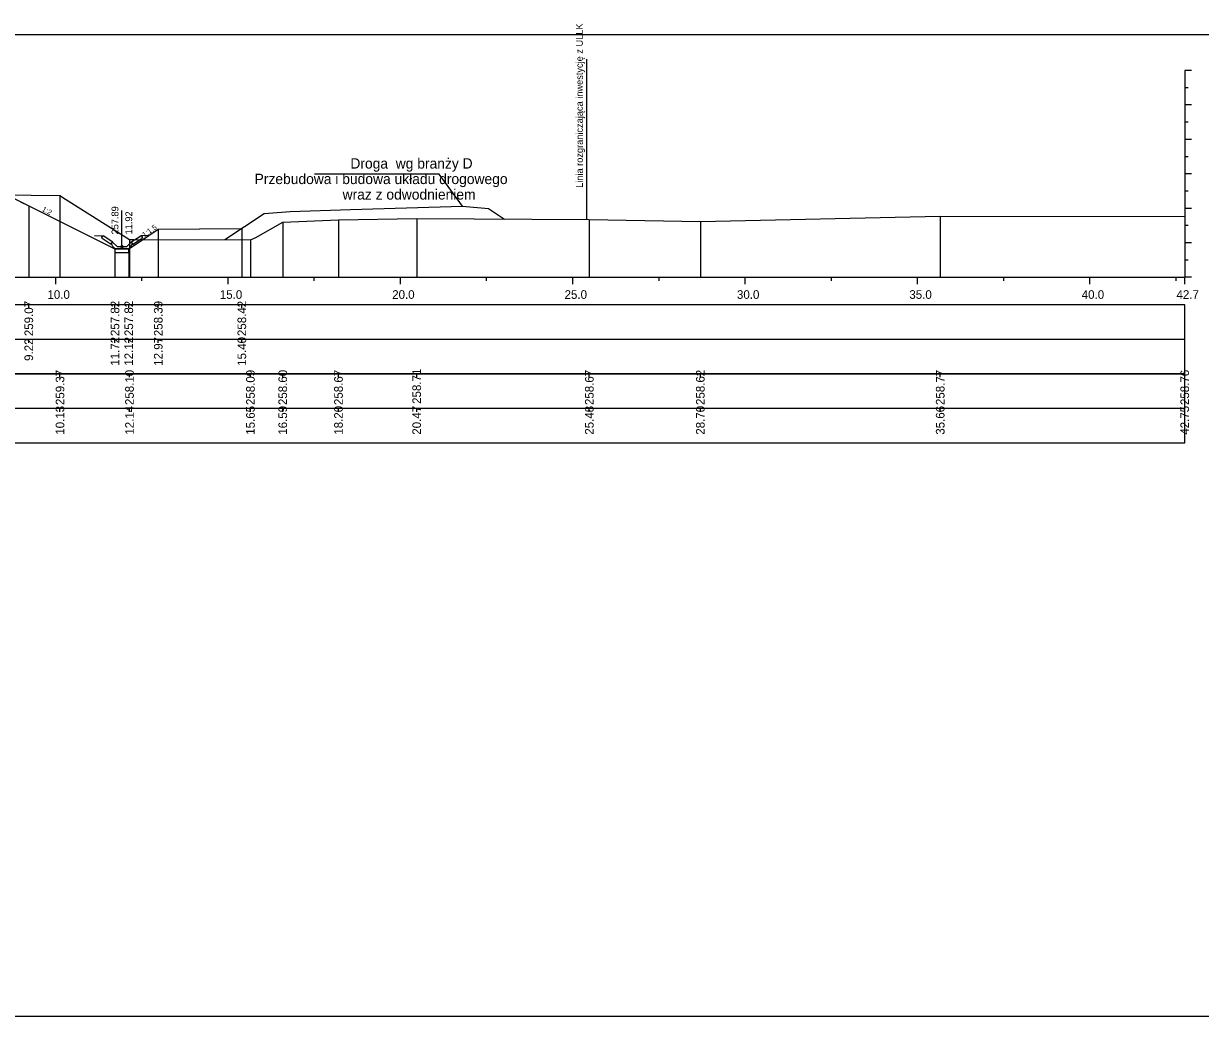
# Model space of a CAD drawing. Extents: x 6516023 to 6560129, y 5513077 to 5529206.
# Drawn here: x 6517046.78 to 6517080.92, y 5514518.16 to 5514546.97 of the extents above; entities that cross this region are included whole.
import ezdxf

# ---------------------------------------------------------------- set-up
doc = ezdxf.new("R2010")
doc.units = 0
for name, color, linetype in [('IR_default', 7, 'Continuous'), ('TOR_PRZEK_P-inne branze', 7, 'Continuous'), ('TOR_PRZEK_P-odwodnienie', 7, 'Continuous'), ('TOR_PRZEK_P-opisy', 7, 'Continuous'), ('TOR_PRZEK_P-tabelka istniejace', 7, 'Continuous'), ('TOR_PRZEK_P-tabelka projektowane', 7, 'Continuous'), ('TOR_PRZEK_P-teren istniejacy', 7, 'Continuous'), ('TOR_PRZEK_P-uklad odniesienia', 7, 'Continuous'), ('TOR_PRZEK_P-warstwa ochronna II', 7, 'Continuous'), ('TOR_PS_T-granica PKP-projektowana', 7, 'Continuous'), ('TOR_RAMKI-ramka+tabelka 1', 7, 'Continuous')]:
    doc.layers.add(name, color=color, linetype=linetype)

msp = doc.modelspace()

# ---------------------------------------------------------------- linework, layer by layer
at = {"layer": 'IR_default'}
msp.add_lwpolyline([(6517046.697, 5514541.797), (6517046.933, 5514541.679), (6517048.755, 5514540.768), (6517049.432, 5514540.429), (6517049.724, 5514540.429), (6517049.832, 5514540.429), (6517050.259, 5514540.713), (6517050.417, 5514540.819), (6517050.614, 5514540.95), (6517050.687, 5514540.999), (6517053.08, 5514541.023), (6517053.112, 5514541.023)], dxfattribs=at)
at = {"layer": 'TOR_PRZEK_P-inne branze'}
for p, q in [((6517058.841, 5514542.601), (6517055.217, 5514542.601)), ((6517059.517, 5514541.666), (6517058.841, 5514542.601))]:
    msp.add_line(p, q, dxfattribs=at)
msp.add_lwpolyline([(6517052.624, 5514540.698), (6517053.763, 5514541.457), (6517054.514, 5514541.517), (6517056.265, 5514541.569), (6517059.517, 5514541.666), (6517060.267, 5514541.606), (6517060.731, 5514541.297)], dxfattribs=at)
at = {"layer": 'TOR_PRZEK_P-odwodnienie'}
for p, q in [((6517049.633, 5514540.499), (6517049.633, 5514541.543)), ((6517049.368, 5514540.625), (6517049.088, 5514540.812)), ((6517049.897, 5514540.625), (6517050.178, 5514540.812)), ((6517049.324, 5514540.558), (6517049.063, 5514540.732)), ((6517049.335, 5514540.575), (6517049.324, 5514540.558)), ((6517049.325, 5514540.594), (6517049.373, 5514540.618)), ((6517049.368, 5514540.625), (6517049.36, 5514540.612)), ((6517049.493, 5514540.499), (6517049.373, 5514540.618)), ((6517049.443, 5514540.429), (6517049.823, 5514540.429)), ((6517049.493, 5514540.499), (6517049.773, 5514540.499)), ((6517049.773, 5514540.499), (6517049.893, 5514540.618)), ((6517049.893, 5514540.618), (6517049.94, 5514540.594)), ((6517049.897, 5514540.625), (6517049.906, 5514540.612)), ((6517049.931, 5514540.575), (6517049.942, 5514540.558)), ((6517049.942, 5514540.558), (6517050.203, 5514540.732))]:
    msp.add_line(p, q, dxfattribs=at)
for points in [[(6517048.841, 5514540.823), (6517049.088, 5514540.812)], [(6517049.038, 5514540.785), (6517049.088, 5514540.812)], [(6517049.038, 5514540.785), (6517049.063, 5514540.732)], [(6517050.424, 5514540.823), (6517050.178, 5514540.812)], [(6517050.228, 5514540.785), (6517050.178, 5514540.812)], [(6517050.228, 5514540.785), (6517050.203, 5514540.732)], [(6517049.36, 5514540.612), (6517049.325, 5514540.594)], [(6517049.373, 5514540.499), (6517049.325, 5514540.594)], [(6517049.325, 5514540.594), (6517049.335, 5514540.575)], [(6517049.443, 5514540.429), (6517049.373, 5514540.499)], [(6517049.432, 5514540.429), (6517049.432, 5514540.429), (6517049.432, 5514540.429), (6517049.432, 5514540.428), (6517049.432, 5514540.429), (6517049.433, 5514540.428), (6517049.432, 5514540.429), (6517049.433, 5514540.429)], [(6517049.433, 5514540.428), (6517049.432, 5514540.429), (6517049.433, 5514540.428), (6517049.432, 5514540.428), (6517049.433, 5514540.428), (6517049.433, 5514540.428), (6517049.433, 5514540.428), (6517049.433, 5514540.429)], [(6517049.833, 5514540.429), (6517049.433, 5514540.429), (6517049.433, 5514540.329), (6517049.833, 5514540.329), (6517049.833, 5514540.429)], [(6517049.823, 5514540.429), (6517049.893, 5514540.499)], [(6517049.832, 5514540.429), (6517049.832, 5514540.429), (6517049.832, 5514540.429), (6517049.832, 5514540.428), (6517049.832, 5514540.429), (6517049.833, 5514540.428), (6517049.832, 5514540.429), (6517049.833, 5514540.429)], [(6517049.833, 5514540.428), (6517049.832, 5514540.429), (6517049.833, 5514540.428), (6517049.832, 5514540.428), (6517049.833, 5514540.428), (6517049.833, 5514540.428), (6517049.833, 5514540.428), (6517049.833, 5514540.429)], [(6517049.893, 5514540.499), (6517049.94, 5514540.594)], [(6517049.906, 5514540.612), (6517049.941, 5514540.594)], [(6517049.941, 5514540.594), (6517049.931, 5514540.575)]]:
    msp.add_lwpolyline(points, dxfattribs=at)
msp.add_circle((6517049.633, 5514540.499), 0.035, dxfattribs=at)
at = {"layer": 'TOR_PRZEK_P-tabelka istniejace'}
for p, q in [((6517047.838, 5514536.706), (6517047.838, 5514536.806)), ((6517049.854, 5514536.706), (6517049.854, 5514536.806)), ((6517053.362, 5514536.706), (6517053.362, 5514536.806)), ((6517054.299, 5514536.706), (6517054.299, 5514536.806)), ((6517055.916, 5514536.706), (6517055.916, 5514536.806)), ((6517058.184, 5514536.706), (6517058.184, 5514536.806)), ((6517063.192, 5514536.706), (6517063.192, 5514536.806)), ((6517066.412, 5514536.706), (6517066.412, 5514536.806)), ((6517073.37, 5514536.706), (6517073.37, 5514536.806)), ((6517080.463, 5514536.706), (6517080.463, 5514536.806)), ((6516996.663, 5514535.806), (6517080.463, 5514535.806)), ((6517047.838, 5514535.706), (6517047.838, 5514535.806)), ((6517049.854, 5514535.706), (6517049.854, 5514535.806)), ((6517053.362, 5514535.706), (6517053.362, 5514535.806)), ((6517054.299, 5514535.706), (6517054.299, 5514535.806)), ((6517055.916, 5514535.706), (6517055.916, 5514535.806)), ((6517058.184, 5514535.706), (6517058.184, 5514535.806)), ((6517063.192, 5514535.706), (6517063.192, 5514535.806)), ((6517066.412, 5514535.706), (6517066.412, 5514535.806)), ((6517073.37, 5514535.706), (6517073.37, 5514535.806)), ((6517080.463, 5514535.706), (6517080.463, 5514535.806))]:
    msp.add_line(p, q, dxfattribs=at)
for points in [[(6517047.838, 5514541.978), (6517047.838, 5514539.806), (6517047.838, 5514539.676), (6517047.838, 5514539.606)], [(6517054.299, 5514541.206), (6517054.299, 5514539.806), (6517054.299, 5514539.676), (6517054.299, 5514539.606)], [(6517055.916, 5514541.277), (6517055.916, 5514539.806), (6517055.916, 5514539.676), (6517055.916, 5514539.606)], [(6517058.184, 5514541.316), (6517058.184, 5514539.806), (6517058.184, 5514539.676), (6517058.184, 5514539.606)], [(6517063.192, 5514541.279), (6517063.192, 5514539.806), (6517063.192, 5514539.676), (6517063.192, 5514539.606)], [(6517066.412, 5514541.228), (6517066.412, 5514539.806), (6517066.412, 5514539.676), (6517066.412, 5514539.606)], [(6517073.37, 5514541.378), (6517073.37, 5514539.806), (6517073.37, 5514539.676), (6517073.37, 5514539.606)], [(6517080.463, 5514541.37), (6517080.463, 5514539.806), (6517080.463, 5514539.676), (6517080.463, 5514539.606)], [(6517049.854, 5514540.706), (6517049.854, 5514539.806), (6517049.854, 5514539.676), (6517049.854, 5514539.606)], [(6517053.362, 5514540.696), (6517053.362, 5514539.806), (6517053.362, 5514539.676), (6517053.362, 5514539.606)]]:
    msp.add_lwpolyline(points, dxfattribs=at)
msp.add_lwpolyline([(6516996.663, 5514536.806), (6516996.663, 5514534.806), (6517080.463, 5514534.806), (6517080.463, 5514536.806)], close=True, dxfattribs=at)
at = {"layer": 'TOR_PRZEK_P-tabelka projektowane'}
for p, q in [((6517046.933, 5514538.706), (6517046.933, 5514538.806)), ((6517049.433, 5514538.706), (6517049.433, 5514538.806)), ((6517049.833, 5514538.706), (6517049.833, 5514538.806)), ((6517050.688, 5514538.706), (6517050.688, 5514538.806)), ((6517053.112, 5514538.706), (6517053.112, 5514538.806)), ((6516996.663, 5514537.806), (6517080.463, 5514537.806)), ((6517046.933, 5514537.706), (6517046.933, 5514537.806)), ((6517049.433, 5514537.706), (6517049.433, 5514537.806)), ((6517049.833, 5514537.706), (6517049.833, 5514537.806)), ((6517050.688, 5514537.706), (6517050.688, 5514537.806)), ((6517053.112, 5514537.706), (6517053.112, 5514537.806))]:
    msp.add_line(p, q, dxfattribs=at)
for points in [[(6517046.933, 5514541.679), (6517046.933, 5514539.806), (6517046.933, 5514539.676), (6517046.933, 5514539.606)], [(6517050.688, 5514540.998), (6517050.688, 5514539.806), (6517050.688, 5514539.676), (6517050.688, 5514539.606)], [(6517053.112, 5514541.023), (6517053.112, 5514539.806), (6517053.112, 5514539.676), (6517053.112, 5514539.606)], [(6517049.433, 5514540.428), (6517049.433, 5514539.806), (6517049.433, 5514539.676), (6517049.433, 5514539.606)], [(6517049.833, 5514540.428), (6517049.833, 5514539.806), (6517049.833, 5514539.676), (6517049.833, 5514539.606)]]:
    msp.add_lwpolyline(points, dxfattribs=at)
msp.add_lwpolyline([(6516996.663, 5514538.806), (6516996.663, 5514536.806), (6517080.463, 5514536.806), (6517080.463, 5514538.806)], close=True, dxfattribs=at)
at = {"layer": 'TOR_PRZEK_P-teren istniejacy'}
msp.add_lwpolyline([(6517045.321, 5514542.013), (6517047.838, 5514541.978), (6517047.998, 5514541.878), (6517049.854, 5514540.706), (6517049.984, 5514540.706), (6517053.362, 5514540.696), (6517053.523, 5514540.761), (6517054.299, 5514541.206), (6517055.916, 5514541.277), (6517058.184, 5514541.316), (6517063.192, 5514541.279), (6517066.412, 5514541.228), (6517073.37, 5514541.378), (6517080.463, 5514541.37)], dxfattribs=at)
at = {"layer": 'TOR_PRZEK_P-uklad odniesienia'}
for p, q in [((6517080.463, 5514545.606), (6517080.463, 5514539.606)), ((6517080.663, 5514545.606), (6517080.463, 5514545.606)), ((6517080.563, 5514545.106), (6517080.463, 5514545.106)), ((6517080.663, 5514544.606), (6517080.463, 5514544.606)), ((6517080.563, 5514544.106), (6517080.463, 5514544.106)), ((6517080.663, 5514543.606), (6517080.463, 5514543.606)), ((6517080.563, 5514543.106), (6517080.463, 5514543.106)), ((6517080.663, 5514542.606), (6517080.463, 5514542.606)), ((6517080.563, 5514542.106), (6517080.463, 5514542.106)), ((6517080.663, 5514541.606), (6517080.463, 5514541.606)), ((6517080.563, 5514541.106), (6517080.463, 5514541.106)), ((6517080.663, 5514540.606), (6517080.463, 5514540.606)), ((6517080.563, 5514540.106), (6517080.463, 5514540.106)), ((6517000.463, 5514539.606), (6517080.463, 5514539.606)), ((6517047.713, 5514539.406), (6517047.713, 5514539.606)), ((6517050.213, 5514539.506), (6517050.213, 5514539.606)), ((6517052.713, 5514539.406), (6517052.713, 5514539.606)), ((6517055.213, 5514539.506), (6517055.213, 5514539.606)), ((6517057.713, 5514539.406), (6517057.713, 5514539.606)), ((6517060.213, 5514539.506), (6517060.213, 5514539.606)), ((6517062.713, 5514539.406), (6517062.713, 5514539.606)), ((6517065.213, 5514539.506), (6517065.213, 5514539.606)), ((6517067.713, 5514539.406), (6517067.713, 5514539.606)), ((6517070.213, 5514539.506), (6517070.213, 5514539.606)), ((6517072.713, 5514539.406), (6517072.713, 5514539.606)), ((6517075.213, 5514539.506), (6517075.213, 5514539.606)), ((6517077.713, 5514539.406), (6517077.713, 5514539.606)), ((6517080.213, 5514539.506), (6517080.213, 5514539.606)), ((6517080.463, 5514539.406), (6517080.463, 5514539.606)), ((6517080.663, 5514539.606), (6517080.463, 5514539.606))]:
    msp.add_line(p, q, dxfattribs=at)
at = {"layer": 'TOR_PRZEK_P-warstwa ochronna II'}
msp.add_lwpolyline([(6517021.393, 5514541.001), (6517021.652, 5514540.998), (6517022.237, 5514540.608), (6517022.637, 5514540.608), (6517023.713, 5514541.326), (6517028.734, 5514541.627), (6517029.213, 5514541.946), (6517033.213, 5514542.106), (6517035.463, 5514542.196), (6517037.713, 5514542.286), (6517038.463, 5514542.316), (6517039.713, 5514542.366), (6517039.763, 5514542.365), (6517041.013, 5514542.315), (6517041.763, 5514542.285), (6517046.063, 5514542.113), (6517046.933, 5514541.679), (6517049.433, 5514540.428), (6517049.833, 5514540.428), (6517050.688, 5514540.998), (6517053.112, 5514541.023)], dxfattribs=at)
at = {"layer": 'TOR_PS_T-granica PKP-projektowana'}
msp.add_line((6517063.116, 5514541.28), (6517063.116, 5514545.937), dxfattribs=at)
at = {"layer": 'TOR_RAMKI-ramka+tabelka 1'}
msp.add_lwpolyline([(6516907.013, 5514546.656), (6517154.513, 5514546.656), (6517154.513, 5514518.156), (6516907.013, 5514518.156)], close=True, dxfattribs=at)

# ---------------------------------------------------------------- texts
at = {"layer": 'TOR_PRZEK_P-inne branze'}
for s, p in [('Droga  wg branży D', (6517056.261, 5514542.761)), ('Przebudowa i budowa układu drogowego', (6517053.483, 5514542.311)), ('wraz z odwodnieniem ', (6517056.035, 5514541.861))]:
    msp.add_text(s, height=0.3, dxfattribs=at).set_placement(p)
at = {"layer": 'TOR_PRZEK_P-odwodnienie'}
for s, p in [('257.89', (6517049.533, 5514540.849)), ('11.92', (6517049.933, 5514540.849))]:
    msp.add_text(s, height=0.2, rotation=90, dxfattribs=at).set_placement(p)
at = {"layer": 'TOR_PRZEK_P-opisy'}
for s, rotation, p in [('1:2', 332.9299, (6517047.3, 5514541.536)), ('1:1,5', 34.0701, (6517050.283, 5514540.764))]:
    msp.add_text(s, height=0.15, rotation=rotation, dxfattribs=at).set_placement(p)
at = {"layer": 'TOR_PRZEK_P-tabelka istniejace'}
for s, p in [('259.37', (6517047.963, 5514535.898)), ('258.10', (6517049.979, 5514535.898)), ('258.09', (6517053.487, 5514535.898)), ('258.60', (6517054.424, 5514535.898)), ('258.67', (6517056.041, 5514535.898)), ('258.71', (6517058.309, 5514535.933)), ('258.67', (6517063.317, 5514535.898)), ('258.62', (6517066.537, 5514535.9)), ('258.77', (6517073.495, 5514535.898)), ('258.76', (6517080.588, 5514535.898)), ('10.13', (6517047.963, 5514535.038)), ('12.14', (6517049.979, 5514535.039)), ('15.65', (6517053.487, 5514535.037)), ('16.59', (6517054.424, 5514535.038)), ('18.20', (6517056.041, 5514535.038)), ('20.47', (6517058.309, 5514535.038)), ('25.48', (6517063.317, 5514535.038)), ('28.70', (6517066.537, 5514535.038)), ('35.66', (6517073.495, 5514535.038)), ('42.75', (6517080.588, 5514535.037))]:
    msp.add_text(s, height=0.25, rotation=90, dxfattribs=at).set_placement(p)
at = {"layer": 'TOR_PRZEK_P-tabelka projektowane'}
for s, p in [('259.07', (6517047.058, 5514537.898)), ('257.82', (6517049.558, 5514537.9)), ('257.82', (6517049.958, 5514537.9)), ('258.39', (6517050.813, 5514537.898)), ('258.42', (6517053.237, 5514537.9)), ('9.22', (6517047.058, 5514537.18)), ('11.72', (6517049.558, 5514537.04)), ('12.12', (6517049.958, 5514537.04)), ('12.97', (6517050.813, 5514537.038)), ('15.40', (6517053.237, 5514537.038))]:
    msp.add_text(s, height=0.25, rotation=90, dxfattribs=at).set_placement(p)
at = {"layer": 'TOR_PRZEK_P-uklad odniesienia'}
for s, p in [('10.0', (6517047.474, 5514538.981)), ('15.0', (6517052.474, 5514538.981)), ('20.0', (6517057.474, 5514538.981)), ('25.0', (6517062.474, 5514538.981)), ('30.0', (6517067.474, 5514538.981)), ('35.0', (6517072.474, 5514538.981)), ('40.0', (6517077.474, 5514538.981)), ('42.7', (6517080.224, 5514538.981))]:
    msp.add_text(s, height=0.25, dxfattribs=at).set_placement(p)
at = {"layer": 'TOR_PS_T-granica PKP-projektowana'}
msp.add_text('Linia rozgraniczająca inwestycję z ULLK', height=0.2, rotation=90.0511, dxfattribs=at).set_placement((6517063.006, 5514542.201))

doc.saveas('drawing.dxf')
